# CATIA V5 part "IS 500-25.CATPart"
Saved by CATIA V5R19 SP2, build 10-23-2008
Part number: IS 500-25
Bounding box of the stored display mesh (mm): x -22.494 to 22.494, y -22.494 to 22.494, z 0 to 135
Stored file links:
  C:\Users\Bora\Desktop\3D Katı model\IS serisi\IS 500\IS 500-25.CATPart
  C:\Program Files\Dassault Systemes\B19\intel_a\reffiles\standard\MetricThickPitch.txt
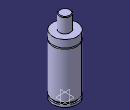
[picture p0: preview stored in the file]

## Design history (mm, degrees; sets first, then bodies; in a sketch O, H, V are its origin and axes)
Body1 (main body)
  Sketch1 on yz-plane, origin (0, 0, 0), H (0, 1, 0), V (0, 0, 1)
    point P1 (22.5, 94.5)
    point P4 (22.5, 92.5)
    point P7 (22.5, 94.5)
    point P8 (22.5, 92.5)
    point P9 (10, 134)
    point P11 (10, 134)
    line L1 (22.5, 94.5) -> (22.5, 108)
    line L2 (22.5, 7.5) -> (22.5, 92.5)
    line L3 (20, 7.5) -> (20, 4)
    arc A1 centre (22.5, 93.5) radius 1 from (22.5, 94.5) to (22.5, 92.5) ccw
    arc A2 centre (9, 134) radius 1 from (10, 134) to (9, 135) ccw
    line L4 (10, 134) -> (10, 108)
    line L5 (22.5, 0) -> (22.5, 4)
    line L6 (9, 135) -> (0, 135)
    point P15 (0, 135)
    line L7 (10, 108) -> (22.5, 108)
    line L8 (0, 0) -> (22.5, 0)
    line L9 (22.5, 4) -> (20, 4)
    line L10 (20, 7.5) -> (22.5, 7.5)
    coincidence: P15 V, P1 P7, P4 P8, P9 P11
    tangency: L6 A2
    horizontal: L7 H, L8 H, L9 H, L10 H
  Shaft1: profile Sketch1, axis Sketch1.V, angle 360
  Sketch2 on face of Shaft1 from Sketch1.L8, origin (0, 0, 0), H (1, 0, 0), V (0, -1, 0)
    point P1 (10, 0)
    distance P1 V = 10
  Hole1: placed by Sketch2, at (10, 0, 0) direction (0, 0, 1), diameter 6.647, depth 13, threaded "M8", thread diameter 8, thread depth 13, pitch 1.25
  Sketch3 on face of Shaft1 from Sketch1.L8, origin (0, 0, 0), H (1, 0, 0), V (0, -1, 0)
    point P1 (-10, 0)
    distance P1 V = 10
  Hole2: placed by Sketch3, at (-10, 0, 0) direction (0, 0, 1), diameter 6.647, depth 13, threaded "M8", thread diameter 8, thread depth 13, pitch 1.25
